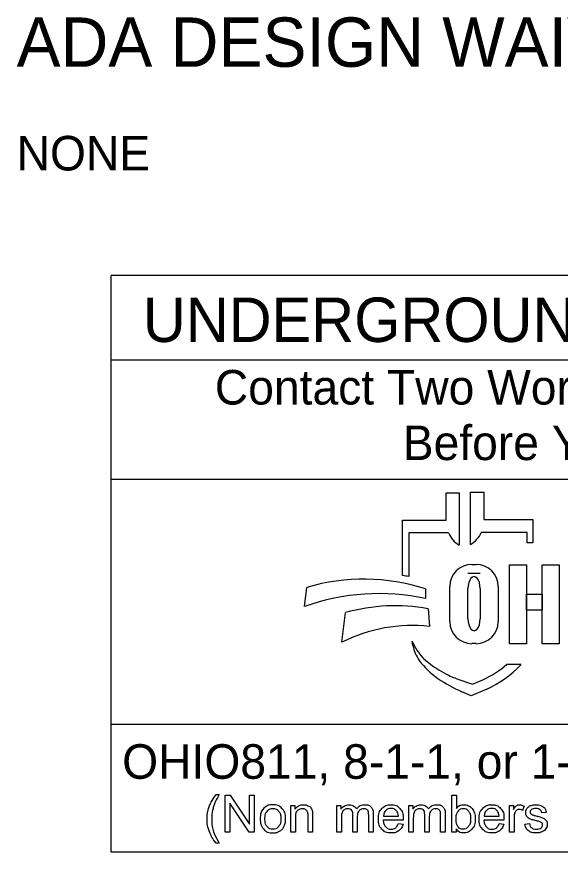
# Model space of a CAD drawing. Extents: x -5.4 to 71.3, y -12 to 22.
# Drawn here: x 1.995 to 4.196, y 2.143 to 5.529 of the extents above; entities that cross this region are included whole.
import ezdxf

# ---------------------------------------------------------------- set-up
doc = ezdxf.new("R2010")
doc.units = 0
doc.layers.add('SH_Data', color=7, linetype='Continuous')
doc.layers.add('SH_Text', color=7, linetype='Continuous')

msp = doc.modelspace()

# ---------------------------------------------------------------- linework, layer by layer
at = {"layer": 'SH_Data'}
for p, q in [((2.3775, 2.1428), (2.3775, 4.4803)), ((6.6275, 4.4803), (2.3775, 4.4803)), ((2.3775, 4.1387), (6.6275, 4.1387)), ((2.3775, 3.6553), (6.6275, 3.6553)), ((6.6275, 2.6607), (2.3775, 2.6607)), ((6.6275, 2.1428), (2.3775, 2.1428))]:
    msp.add_line(p, q, dxfattribs=at)
at = {"layer": 'SH_Text'}
for p, q in [((3.7335, 3.4883), (3.7335, 3.5998)), ((3.7335, 3.5998), (3.7872, 3.5998)), ((3.7872, 3.5998), (3.7872, 3.3877)), ((3.8329, 3.39), (3.8329, 3.6021)), ((3.8329, 3.6021), (3.8865, 3.6021)), ((3.8865, 3.6021), (3.8865, 3.4906)), ((3.5576, 3.2644), (3.5576, 3.4883)), ((3.5576, 3.4883), (3.7335, 3.4883)), ((3.8865, 3.4906), (4.0857, 3.4906)), ((4.0857, 3.4906), (4.0857, 3.3968)), ((3.5828, 3.4369), (3.5828, 3.26)), ((3.7439, 3.4369), (3.5828, 3.4369)), ((4.0625, 3.4392), (3.8761, 3.4392)), ((4.0625, 3.3968), (4.0625, 3.4392)), ((4.0857, 3.3968), (4.0625, 3.3968)), ((3.8385, 3.3091), (3.8551, 3.3091)), ((3.8718, 3.2721), (3.822, 3.2721)), ((3.7491, 3.0776), (3.7491, 3.2196)), ((3.9445, 3.2196), (3.9445, 3.0776)), ((3.1602, 3.1381), (3.1696, 3.2162)), ((3.6509, 3.2097), (3.6509, 3.1709)), ((3.822, 3.089), (3.822, 3.2114)), ((3.8718, 3.2114), (3.8718, 3.089)), ((3.6608, 3.1291), (3.6671, 3.0582)), ((3.312, 2.9936), (3.3267, 3.1137)), ((3.5997, 2.9807), (3.5967, 2.9986)), ((3.8551, 2.9882), (3.8385, 2.9882)), ((3.98, 2.9048), (4.0375, 2.9048)), ((3.7816, 2.8444), (3.841, 2.8239)), ((3.841, 2.8239), (3.8821, 2.8417)), ((3.835, 2.7769), (3.7976, 2.7934)), ((3.8983, 2.8044), (3.835, 2.7769))]:
    msp.add_line(p, q, dxfattribs=at)
for points in [[(3.991, 3.3081), (4.0589, 3.3081), (4.0589, 2.9881), (3.991, 2.9881)], [(4.1231, 3.3081), (4.1911, 3.3081), (4.1911, 2.9881), (4.1231, 2.9881)], [(4.0589, 3.1882), (4.1231, 3.1882), (4.1231, 3.1242), (4.0589, 3.1242)]]:
    msp.add_lwpolyline(points, close=True, dxfattribs=at)
for points in [[(2.8021, 2.3766), (2.8153, 2.3766)], [(2.8389, 2.2239), (2.8389, 2.3741), (2.8592, 2.3741), (2.9382, 2.2561), (2.9382, 2.3741), (2.9572, 2.3741), (2.9572, 2.2239), (2.9369, 2.2239), (2.8579, 2.3419), (2.8579, 2.2239), (2.8389, 2.2239)], [(3.7743, 2.2239), (3.7573, 2.2239), (3.7573, 2.3741), (3.7757, 2.3741), (3.7757, 2.3206)], [(3.1048, 2.2239), (3.1048, 2.3328), (3.1214, 2.3328), (3.1214, 2.3173)], [(3.2912, 2.2239), (3.2912, 2.3328), (3.3077, 2.3328), (3.3077, 2.3174)], [(3.5826, 2.2239), (3.5826, 2.3328), (3.5991, 2.3328), (3.5991, 2.3174)], [(3.9904, 2.2239), (3.9904, 2.3328), (4.007, 2.3328), (4.007, 2.3163)], [(4.0495, 2.3293), (4.043, 2.3122)], [(4.1394, 2.3046), (4.1213, 2.3022)], [(3.1233, 2.2833), (3.1233, 2.2239), (3.1048, 2.2239)], [(3.1932, 2.2908), (3.1932, 2.2239), (3.1748, 2.2239), (3.1748, 2.2901)], [(3.3097, 2.2803), (3.3097, 2.2239), (3.2912, 2.2239)], [(3.3743, 2.2871), (3.3743, 2.2239), (3.3559, 2.2239), (3.3559, 2.2946)], [(3.4388, 2.2986), (3.4388, 2.2239), (3.4203, 2.2239), (3.4203, 2.2924)], [(3.56, 2.2736), (3.4788, 2.2736)], [(3.4799, 2.2887), (3.5406, 2.2887)], [(3.601, 2.2803), (3.601, 2.2239), (3.5826, 2.2239)], [(3.6657, 2.2871), (3.6657, 2.2239), (3.6473, 2.2239), (3.6473, 2.2946)], [(3.7301, 2.2986), (3.7301, 2.2239), (3.7117, 2.2239), (3.7117, 2.2924)], [(3.968, 2.2736), (3.8868, 2.2736)], [(3.8879, 2.2887), (3.9486, 2.2887)], [(4.0088, 2.2809), (4.0088, 2.2239), (3.9904, 2.2239)], [(3.5404, 2.2591), (3.5595, 2.2567)], [(3.7743, 2.2375), (3.7743, 2.2239)], [(3.9484, 2.2591), (3.9675, 2.2567)], [(4.053, 2.2564), (4.0712, 2.2593)], [(2.8153, 2.1798), (2.8021, 2.1798)]]:
    msp.add_lwpolyline(points, dxfattribs=at)
for centre, radius, start, end in [((3.8353, 3.4736), 0.0985, 201.9296, 240.7469), ((3.7847, 3.476), 0.0985, 299.2531, 338.0704), ((3.8385, 3.2196), 0.0895, 90, 180), ((3.8551, 3.2196), 0.0895, 0, 90), ((3.4295, 2.4554), 0.8191, 79.2074, 81.0007), ((3.3997, 2.4302), 0.8191, 72.1402, 106.3144), ((3.4628, 2.2991), 0.8919, 77.8238, 109.8274), ((3.5267, 2.4094), 0.7322, 79.44, 105.8467), ((3.5987, 2.4262), 0.6357, 83.8248, 116.8021), ((3.8385, 3.0776), 0.0895, 180, 270), ((3.8551, 3.0776), 0.0895, 270, 0), ((3.7841, 3.0707), 0.2008, 201.0457, 232.5314), ((3.741, 3.0048), 0.1433, 189.6817, 216.0884), ((3.8747, 3.1022), 0.3088, 216.0884, 235.7167), ((3.9766, 3.3219), 0.5173, 232.5314, 241.794), ((3.7387, 3.1722), 0.3602, 293.4582, 312.0712), ((3.7387, 3.1722), 0.401, 293.4582, 317.8286), ((4.0412, 3.3465), 0.6044, 235.7167, 246.2325), ((3.8914, 3.1631), 0.3371, 241.794, 250.9821)]:
    msp.add_arc(centre, radius, start, end, dxfattribs=at)
for centre, start_param, end_param in [((3.8469, 3.2114), 4.712389, 7.853982), ((3.8469, 3.089), 1.570796, 4.712389)]:
    msp.add_ellipse(centre, major_axis=(0, 0.0484), ratio=0.514403, start_param=start_param, end_param=end_param, dxfattribs=at)
for points in [[(2.8021, 2.1798), (2.7869, 2.199), (2.7763, 2.2248), (2.7657, 2.2506), (2.7657, 2.2783), (2.7657, 2.3026), (2.7736, 2.325), (2.7829, 2.3509), (2.8021, 2.3766)], [(2.8153, 2.3766), (2.8029, 2.3553), (2.7989, 2.3462), (2.7927, 2.332), (2.7891, 2.3167), (2.7847, 2.2975), (2.7847, 2.2782), (2.7847, 2.2289), (2.8153, 2.1798)], [(2.9814, 2.2783), (2.9814, 2.3085), (2.9981, 2.3231), (3.0122, 2.3352), (3.0323, 2.3352), (3.0547, 2.3352), (3.069, 2.3205), (3.0832, 2.3058), (3.0832, 2.2799), (3.0832, 2.2589), (3.0769, 2.2469), (3.0706, 2.2348), (3.0586, 2.2282), (3.0466, 2.2215), (3.0323, 2.2215), (3.0095, 2.2215), (2.9954, 2.2362), (2.9814, 2.2508), (2.9814, 2.2783)], [(3.0003, 2.2783), (3.0003, 2.2574), (3.0094, 2.247), (3.0185, 2.2366), (3.0323, 2.2366), (3.046, 2.2366), (3.0551, 2.2471), (3.0642, 2.2575), (3.0642, 2.279), (3.0642, 2.2991), (3.0551, 2.3095), (3.0459, 2.3199), (3.0323, 2.3199), (3.0185, 2.3199), (3.0094, 2.3096), (3.0003, 2.2992), (3.0003, 2.2783)], [(3.1214, 2.3173), (3.1334, 2.3352), (3.156, 2.3352), (3.1659, 2.3352), (3.1741, 2.3316), (3.1823, 2.3281), (3.1864, 2.3224), (3.1905, 2.3166), (3.1922, 2.3087), (3.1932, 2.3036), (3.1932, 2.2908)], [(3.1748, 2.2901), (3.1748, 2.3013), (3.1726, 2.3069), (3.1705, 2.3125), (3.165, 2.3158), (3.1595, 2.3191), (3.1521, 2.3191), (3.1404, 2.3191), (3.1318, 2.3117), (3.1233, 2.3042), (3.1233, 2.2833)], [(3.3077, 2.3174), (3.3128, 2.3254), (3.3214, 2.3303), (3.3299, 2.3352), (3.3407, 2.3352), (3.3528, 2.3352), (3.3606, 2.3301), (3.3683, 2.3251), (3.3715, 2.3161), (3.3844, 2.3352), (3.4051, 2.3352), (3.4213, 2.3352), (3.43, 2.3262), (3.4388, 2.3172), (3.4388, 2.2986)], [(3.3559, 2.2946), (3.3559, 2.3069), (3.3514, 2.313), (3.3469, 2.3191), (3.3366, 2.3191), (3.3288, 2.3191), (3.3222, 2.315), (3.3156, 2.311), (3.3126, 2.3031), (3.3097, 2.2952), (3.3097, 2.2803)], [(3.4203, 2.2924), (3.4203, 2.3035), (3.4185, 2.3083), (3.4168, 2.3132), (3.412, 2.3162), (3.4073, 2.3191), (3.401, 2.3191), (3.3895, 2.3191), (3.3819, 2.3115), (3.3743, 2.3039), (3.3743, 2.2871)], [(3.5595, 2.2567), (3.555, 2.24), (3.5428, 2.2307), (3.5306, 2.2215), (3.5117, 2.2215), (3.4878, 2.2215), (3.4738, 2.2362), (3.4598, 2.2509), (3.4598, 2.2774), (3.4598, 2.3049), (3.474, 2.32), (3.4881, 2.3352), (3.5106, 2.3352), (3.5324, 2.3352), (3.5463, 2.3203), (3.5601, 2.3055), (3.5601, 2.2785), (3.5601, 2.2769), (3.56, 2.2736)], [(3.5406, 2.2887), (3.5394, 2.3025), (3.5337, 2.3094), (3.5249, 2.3201), (3.5108, 2.3201), (3.4981, 2.3201), (3.4894, 2.3115), (3.4808, 2.303), (3.4799, 2.2887)], [(3.5991, 2.3174), (3.6042, 2.3254), (3.6127, 2.3303), (3.6212, 2.3352), (3.6321, 2.3352), (3.6442, 2.3352), (3.6519, 2.3301), (3.6597, 2.3251), (3.6628, 2.3161), (3.6758, 2.3352), (3.6965, 2.3352), (3.7127, 2.3352), (3.7214, 2.3262), (3.7301, 2.3172), (3.7301, 2.2986)], [(3.6473, 2.2946), (3.6473, 2.3069), (3.6428, 2.313), (3.6383, 2.3191), (3.628, 2.3191), (3.6202, 2.3191), (3.6136, 2.315), (3.607, 2.311), (3.604, 2.3031), (3.601, 2.2952), (3.601, 2.2803)], [(3.7117, 2.2924), (3.7117, 2.3035), (3.7099, 2.3083), (3.7081, 2.3132), (3.7034, 2.3162), (3.6987, 2.3191), (3.6923, 2.3191), (3.6809, 2.3191), (3.6733, 2.3115), (3.6657, 2.3039), (3.6657, 2.2871)], [(3.7741, 2.2792), (3.7741, 2.2596), (3.7794, 2.2509), (3.7881, 2.2366), (3.8029, 2.2366), (3.815, 2.2366), (3.8238, 2.2471), (3.8326, 2.2576), (3.8326, 2.2784), (3.8326, 2.2998), (3.8241, 2.3099), (3.8157, 2.3201), (3.8038, 2.3201), (3.7917, 2.3201), (3.7829, 2.3096), (3.7741, 2.299), (3.7741, 2.2792)], [(3.7757, 2.3206), (3.7874, 2.3352), (3.8055, 2.3352), (3.8155, 2.3352), (3.8245, 2.3311), (3.8335, 2.3271), (3.8392, 2.3198), (3.845, 2.3124), (3.8483, 2.3021), (3.8516, 2.2918), (3.8516, 2.28), (3.8516, 2.252), (3.8378, 2.2368), (3.8239, 2.2215), (3.8046, 2.2215), (3.7853, 2.2215), (3.7743, 2.2375)], [(3.9675, 2.2567), (3.963, 2.24), (3.9508, 2.2307), (3.9386, 2.2215), (3.9196, 2.2215), (3.8958, 2.2215), (3.8818, 2.2362), (3.8678, 2.2509), (3.8678, 2.2774), (3.8678, 2.3049), (3.882, 2.32), (3.8961, 2.3352), (3.9186, 2.3352), (3.9404, 2.3352), (3.9543, 2.3203), (3.9681, 2.3055), (3.9681, 2.2785), (3.9681, 2.2769), (3.968, 2.2736)], [(3.9486, 2.2887), (3.9474, 2.3025), (3.9417, 2.3094), (3.9328, 2.3201), (3.9188, 2.3201), (3.9061, 2.3201), (3.8974, 2.3115), (3.8888, 2.303), (3.8879, 2.2887)], [(4.007, 2.3163), (4.0133, 2.3278), (4.0187, 2.3315), (4.0241, 2.3352), (4.0305, 2.3352), (4.0398, 2.3352), (4.0495, 2.3293)], [(4.043, 2.3122), (4.0363, 2.3162), (4.0295, 2.3162), (4.0235, 2.3162), (4.0187, 2.3125), (4.0139, 2.3089), (4.0119, 2.3024), (4.0088, 2.2926), (4.0088, 2.2809)], [(4.1213, 2.3022), (4.1201, 2.3106), (4.1142, 2.3153), (4.1083, 2.3201), (4.0975, 2.3201), (4.0848, 2.3201), (4.0794, 2.3159), (4.0739, 2.3116), (4.0739, 2.306), (4.0739, 2.3024), (4.0762, 2.2995), (4.0785, 2.2966), (4.0833, 2.2946), (4.086, 2.2936), (4.0996, 2.2899), (4.1192, 2.2847), (4.1269, 2.2813), (4.1347, 2.278), (4.1391, 2.2717), (4.1435, 2.2653), (4.1435, 2.2559), (4.1435, 2.2467), (4.1381, 2.2386), (4.1327, 2.2304), (4.1226, 2.226), (4.1124, 2.2215), (4.0996, 2.2215), (4.0784, 2.2215), (4.0672, 2.2303), (4.0561, 2.2391), (4.053, 2.2564)], [(4.0712, 2.2593), (4.0727, 2.2483), (4.0798, 2.2425), (4.0868, 2.2366), (4.0995, 2.2366), (4.1122, 2.2366), (4.1184, 2.2418), (4.1245, 2.247), (4.1245, 2.254), (4.1245, 2.2602), (4.1191, 2.2638), (4.1153, 2.2663), (4.1002, 2.2701), (4.0799, 2.2752), (4.072, 2.2789), (4.0642, 2.2827), (4.0601, 2.2893), (4.0561, 2.2959), (4.0561, 2.3038), (4.0561, 2.3111), (4.0594, 2.3173), (4.0628, 2.3235), (4.0685, 2.3276), (4.0728, 2.3308), (4.0803, 2.333), (4.0877, 2.3352), (4.0962, 2.3352), (4.109, 2.3352), (4.1187, 2.3315), (4.1284, 2.3278), (4.133, 2.3215), (4.1377, 2.3152), (4.1394, 2.3046)], [(3.4788, 2.2736), (3.4799, 2.2557), (3.489, 2.2462), (3.4981, 2.2366), (3.5117, 2.2366), (3.5219, 2.2366), (3.5291, 2.242), (3.5362, 2.2473), (3.5404, 2.2591)], [(3.8868, 2.2736), (3.8879, 2.2557), (3.897, 2.2462), (3.9061, 2.2366), (3.9197, 2.2366), (3.9299, 2.2366), (3.937, 2.242), (3.9442, 2.2473), (3.9484, 2.2591)]]:
    msp.add_open_spline(points, degree=3, dxfattribs=at)

# ---------------------------------------------------------------- texts
for s, height, p in [('ADA DESIGN WAIVERS', 0.2, (1.9944, 5.3256)), ('NONE', 0.14, (1.9944, 4.9056)), ('UNDERGROUND UTILITIES', 0.18, (2.5057, 4.2106)), ('Contact Two Working Days', 0.14, (2.7972, 3.9571)), ('Before You Dig', 0.14, (3.5583, 3.7321)), ('OHIO811, 8-1-1, or 1-800-362-2764', 0.14, (2.422, 2.4406))]:
    msp.add_text(s, height=height, dxfattribs=at).set_placement(p)

doc.saveas('drawing.dxf')
